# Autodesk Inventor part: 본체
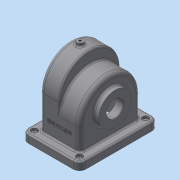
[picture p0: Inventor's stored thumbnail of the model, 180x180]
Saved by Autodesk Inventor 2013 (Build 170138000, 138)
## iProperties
Created: 2017-11
Part Number: 본체
Material: 일반
Document SubType Name: Modeling
Designer: dgall
Density: 1 g/cm^3
Author: dgall
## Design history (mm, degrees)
sketch "스케치1"
  geometry: L1 (58, 0)-(58, -42); L2 (58, -42)-(-58, -42); L3 (-58, -42)-(-58, 0); A1 r 58 centre (0, 0) between (58, 0) and (-58, 0); 2 further points
  constraints: 6 end point, 2 coincident, 2 horizontal alignment, 2 point on circle, 2 tangent, 1 centre point, 1 parallel
  dimensions: "d2" = 116 distance of L1.end L2.end; "d3" = 42 distance of L1.start L1.end; "d4" = 42 distance from line of L2 L1.start
extrude "돌출1" new body sketch "스케치1" distance "d5" = 38; taper "d6" = 0 deg
sketch "스케치3"
  geometry: L1 (-42, -58)-(-42, 58) reference; L2 (23, -58)-(-42, -58); L3 (-42, -58)-(-42, 58); L4 (23, 58)-(-42, 58); A1 r 58 centre (0, 0) between (0, -58) and (0, 58) reference; A2 r 58 centre (23, 0) between (23, -58) and (23, 58)
  constraints: 6 end point, 2 point on circle, 2 tangent, 1 centre point, 1 horizontal alignment
  dimensions: "d9" = 58 radius of A2; "d10" = 65 distance from line of A2.centre L3
extrude "돌출2" join sketch "스케치3" distance "d11" = 38; taper "d12" = 0 deg
feature "쉘1" dims "d13" = 5
sketch "스케치4"
  geometry: L1 (5, 111)-(71, 111) reference; L2 (71, 111)-(71, 5) reference; L3 (71, 5)-(5, 5) reference; L4 (5, 5)-(5, 111) reference; L5 (93, 133)-(93, -17); L6 (93, -17)-(-17, -17); L7 (-17, -17)-(-17, 133); L8 (-17, 133)-(93, 133); 3 further points
  constraints: 8 end point, 2 midpoint, 2 parallel, 1 horizontal, 1 horizontal alignment, 1 perpendicular, 1 vertical alignment
  dimensions: "d14" = 110 distance of L7.end L5.start; "d15" = 150 distance of L5.start L5.end
extrude "돌출3" join sketch "스케치4" distance "d16" = 15; taper "d17" = 0 deg
sketch "스케치5"
  geometry: L1 (-57, -75)-(-57, 75) reference; C1 r 37.5 at (8, 0); 1 further point
  constraints: 1 centre point, 1 horizontal alignment
  dimensions: "d18" = 75 diameter of C1; "d19" = 65 distance from line of C1.centre L1
extrude "돌출4" join sketch "스케치5" distance "d20" = 9; taper "d21" = 0 deg
sketch "스케치6"
  geometry: L1 (57, 75)-(57, -75) reference; C1 r 31 at (-8, 0); A1 r 58 centre (0, 0) between (0, 58) and (0, -58) reference
  constraints: 1 centre point, 1 horizontal alignment
  dimensions: "d22" = 62 diameter of C1; "d23" = 65 distance from line of L1 C1.centre
extrude "돌출5" join sketch "스케치6" distance "d24" = 10; taper "d25" = 0 deg
hole "구멍1" diameter "d28" = 32; stored, may be unused: countersink angle "d32" = 90 deg, drill point angle "d34" = 118 deg; dims "d26" = 10, "d27" = 10, "d29" = 6, "d30" = 4, "d31" = 2, "d33" = 8
node "작업 평면1"
sketch "스케치8"
  geometry: L1 (-76, 116)-(-76, 0) reference; C1 r 6 at (-57, 58); 1 further point
  constraints: 1 centre point, 1 horizontal alignment
  dimensions: "d36" = 12 diameter of C1; "d37" = 19 distance from line of L1 C1.centre
extrude "돌출6" join sketch "스케치8" stored distance "d38" = 10; taper "d39" = 0 deg
hole "구멍2" diameter "d42" = 4.459; stored, may be unused: countersink angle "d46" = 90 deg, drill point angle "d48" = 0 deg; dims "d40" = 10, "d41" = 10, "d43" = 6, "d44" = 4, "d45" = 2, "d47" = 8
sketch "스케치9"
  geometry: C1 r 16 at (0, 0) reference; 2 further points
  constraints: 1 horizontal alignment
  dimensions: "d49" = 26 distance of point (26, 0) C1.centre
hole "구멍3" sketch "스케치9" at (26, 0) diameter "d50" = 2.459; stored, may be unused: countersink angle "d54" = 90 deg, drill point angle "d56" = 118 deg; dims "d51" = 6, "d52" = 4, "d53" = 2, "d55" = 8
sketch "스케치10"
  geometry: C1 r 16 at (0, 0) reference; 2 further points
  constraints: 1 horizontal alignment
  dimensions: "d60" = 29 distance of C1.centre point (29, 0)
hole "구멍4" sketch "스케치10" at (29, 0) diameter "d61" = 2.459; stored, may be unused: countersink angle "d65" = 90 deg, drill point angle "d67" = 118 deg; dims "d62" = 6, "d63" = 4, "d64" = 2, "d66" = 8
fillet "모깎기1" dims "d71" = 12
hole "구멍5" diameter "d74" = 5; stored, may be unused: countersink angle "d78" = 90 deg, drill point angle "d80" = 118 deg; dims "d72" = 10, "d73" = 10, "d75" = 6, "d76" = 12, "d77" = 5, "d79" = 8
hole "구멍6" diameter "d83" = 5; stored, may be unused: countersink angle "d87" = 90 deg, drill point angle "d89" = 118 deg; dims "d81" = 10, "d82" = 10, "d84" = 6, "d85" = 12, "d86" = 5, "d88" = 8
hole "구멍7" diameter "d92" = 5; stored, may be unused: countersink angle "d96" = 90 deg, drill point angle "d98" = 118 deg; dims "d90" = 10, "d91" = 10, "d93" = 6, "d94" = 12, "d95" = 5, "d97" = 8
hole "구멍8" diameter "d101" = 5; stored, may be unused: countersink angle "d105" = 90 deg, drill point angle "d107" = 118 deg; dims "d99" = 10, "d100" = 10, "d102" = 6, "d103" = 12, "d104" = 5, "d106" = 8
chamfer "모따기1" distance "d108" = 1; stored, may be unused: second distance "d109" = 2, angle "d110" = 45 deg
fillet "모깎기2" dims "d111" = 8
fillet "모깎기3" dims "d112" = 3
fillet "모깎기4" dims "d113" = 3
sketch "스케치11"
  geometry: L1 (73, -18)-(-13, -18) reference; L2 (-8, 62)-(-8, 0) reference; 2 further points
  constraints: 1 other
  dimensions: "d114" = 40 distance from line of L1 point (30, 22); "d115" = 38 distance from line of point (30, 22) L2
extrude "돌출7" join sketch "스케치11" distance "d116" = 0.5; taper "d117" = 0 deg
node "솔리드1"
pattern_circular "원형 패턴1" dims angle "d58" = 360 deg
pattern_circular "원형 패턴2" dims angle "d69" = 360 deg
other parameters: "d35" = -144
